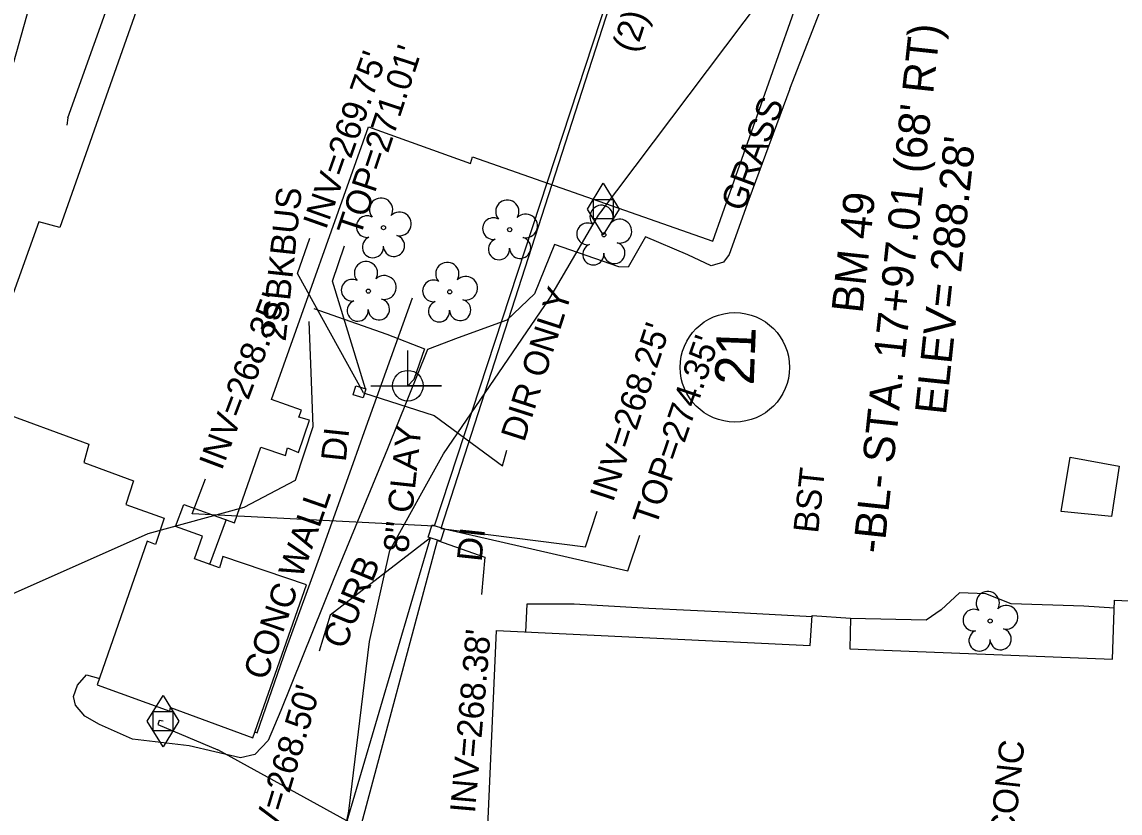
# Model space of a CAD drawing. Extents: x 2100323 to 2109811, y 740376 to 749755.
# Drawn here: x 2105595 to 2105770.6, y 741876.3 to 742002.8 of the extents above; entities that cross this region are included whole.
import ezdxf

# ---------------------------------------------------------------- set-up
doc = ezdxf.new("R2010")
doc.units = 0
for name, color, linetype in [('CTL Sheet Text', 7, 'Continuous'), ('Exist Building', 7, 'Continuous'), ('Exist Building Text', 7, 'Continuous'), ('Exist Property Owner Number CELL', 7, 'Continuous'), ('Exist Roads Change in Surface', 7, 'Continuous'), ('Exist Roads EOP Other', 7, 'Continuous'), ('Exist Roads EOP Other Text', 7, 'Continuous'), ('Exist Roads EOP Text', 7, 'Continuous'), ('Exist Structure Minor Drop Inlet', 7, 'Continuous'), ('Exist Structure Minor Drop Inlet Text', 7, 'Continuous'), ('Exist Structure Minor Drop Inlet Top Elevation', 7, 'Continuous'), ('Exist Structure Minor Pipes HDPE 8 Inch', 7, 'Continuous'), ('Exist Structure Minor Pipes HDPE 8 Inch Invert', 7, 'Continuous'), ('Exist Structure Minor Pipes HDPE 8 Inch Leader', 7, 'Continuous'), ('Exist Structure Minor Pipes HDPE 8 Inch Text', 7, 'Continuous'), ('Exist Structure Minor Pipes RCP 30 Inch', 7, 'Continuous'), ('Exist Structure Minor Pipes RCP 30 Inch Invert', 7, 'Continuous'), ('Exist Structure Minor Pipes RCP 30 Inch Leader', 7, 'Continuous'), ('Exist Structure Minor Pipes RCP 36 Inch', 7, 'Continuous'), ('Exist Structure Minor Pipes RCP 36 Inch Invert', 7, 'Continuous'), ('Exist Structure Minor Pipes RCP 36 Inch Leader', 7, 'Continuous'), ('Exist Structure Minor Pipes RCP 36 Inch Text', 7, 'Continuous'), ('Exist Utilities Gas Meter CELL', 7, 'Continuous'), ('Exist Utilities Gas UG Line SUE LOS B', 7, 'Continuous'), ('Exist Utilities Power Joint Use Telephone CELL', 7, 'Continuous'), ('Exist Utilities Power UG Cable SUE LOS B', 7, 'Continuous'), ('Exist Utilities TV UG Cable SUE LOS B', 7, 'Continuous'), ('Exist Utilities Water UG Line SUE LOS B', 7, 'Continuous'), ('Exist Vegetation Tree CELL', 7, 'Continuous')]:
    doc.layers.add(name, color=color, linetype=linetype)

msp = doc.modelspace()

# ---------------------------------------------------------------- linework, layer by layer
at = {"layer": 'Exist Building'}
for points in [[(2105621.62, 742028.24), (2105601.07, 741969.88), (2105597.69, 741970.78), (2105587.85, 741943.41)], [(2105590.56, 741940.79), (2105605.71, 741935.25), (2105604.88, 741932.34), (2105612.85, 741929.4), (2105611.59, 741925.61), (2105617.73, 741923.43), (2105616.34, 741919.21), (2105615.02, 741919.75), (2105607.01, 741896.76), (2105618.63, 741892.58), (2105618.76, 741893.15), (2105631.93, 741888.31), (2105640.48, 741912.76), (2105627.14, 741917.27), (2105626.57, 741915.46), (2105622.58, 741916.92), (2105623.85, 741920.55), (2105619.55, 741922.08), (2105620.87, 741925.6), (2105629.01, 741922.69), (2105633.22, 741934.75), (2105637.15, 741933.46), (2105637.44, 741934.67), (2105639.24, 741933.94), (2105641.01, 741939.07), (2105639.3, 741939.58), (2105639.68, 741940.69), (2105634.9, 741942.39), (2105650.4, 741985.99), (2105666.71, 741980.11), (2105667.07, 741981.21), (2105705.48, 741967.71), (2105725.59, 742024.56)], [(2105632.26, 741889.23), (2105632.61, 741889.09), (2105637.28, 741902.64), (2105642.8, 741917.71), (2105647.96, 741932.16), (2105649.77, 741937.29), (2105657.47, 741958.64)]]:
    msp.add_lwpolyline(points, dxfattribs=at)
msp.add_lwpolyline([(2105670.9, 741905.44), (2105721.05, 741903.04), (2105721.37, 741907.86), (2105727.5, 741907.41), (2105727.43, 741902.52), (2105769.41, 741900.88), (2105769.76, 741910.32), (2105844.65, 741906.94), (2105842.98, 741859.96), (2105839.73, 741860.04), (2105839.3, 741846.45), (2105817.52, 741847.26), (2105817.67, 741848.94), (2105747.32, 741852.58), (2105747.94, 741861.98), (2105669.16, 741865.67)], close=True, dxfattribs=at)
at = {"layer": 'Exist Property Owner Number CELL'}
msp.add_circle((2105709.01, 741947.53), 8.75, dxfattribs=at)
at = {"layer": 'Exist Roads Change in Surface'}
msp.add_lwpolyline([(2105769.28, 741923.68), (2105761.19, 741924.49), (2105762.63, 741933.18), (2105770.47, 741931.72), (2105769.28, 741923.68)], dxfattribs=at)
at = {"layer": 'Exist Roads EOP Other'}
for points in [[(2105717.81, 741992.04), (2105723.84, 742007.6), (2105728.39, 742018.84), (2105729.19, 742021.25), (2105728.91, 742023.26), (2105727.58, 742024.18), (2105725.48, 742023.47)], [(2105717.81, 741992.04), (2105711.27, 741974.37), (2105708.1, 741965.56), (2105707.2, 741964.35), (2105705.22, 741963.79), (2105701.48, 741965.51), (2105694.75, 741968.38), (2105692.78, 741965.03), (2105691.97, 741963.57), (2105690.48, 741963.59), (2105680.16, 741967.17), (2105676.99, 741959.3), (2105672.53, 741955.06), (2105664.76, 741952.27), (2105659.87, 741950.38), (2105653.45, 741934.5), (2105644.89, 741913.69), (2105636.4, 741892.69), (2105634.38, 741887.87), (2105632.25, 741885.64), (2105629.95, 741885.1), (2105621.73, 741887.04), (2105612.69, 741888.09), (2105607.37, 741890.44), (2105605.07, 741891.77), (2105603.55, 741893.51), (2105603.23, 741894.89), (2105603.89, 741896.72), (2105605.3, 741898.35), (2105607.26, 741897.86), (2105607.38, 741897.83)], [(2105627.64, 741923.18), (2105625.01, 741916.03)], [(2105769.72, 741909.05), (2105764.85, 741909.37), (2105753.19, 741909.71), (2105749.15, 741911.34), (2105744.94, 741911.49), (2105742.02, 741908.76), (2105739.64, 741907.11), (2105727.5, 741907.36)], [(2105721.36, 741907.64), (2105708.58, 741908.34), (2105695.28, 741908.98), (2105683.34, 741909.69), (2105675.73, 741909.67), (2105675.53, 741905.21)]]:
    msp.add_lwpolyline(points, dxfattribs=at)
at = {"layer": 'Exist Structure Minor Drop Inlet'}
for points in [[(2105648.4, 741944.58), (2105649.97, 741944.12), (2105649.55, 741942.67), (2105647.98, 741943.13)], [(2105660.59, 741922.36), (2105662.56, 741921.7), (2105661.91, 741919.74), (2105659.94, 741920.4)]]:
    msp.add_lwpolyline(points, close=True, dxfattribs=at)
at = {"layer": 'Exist Structure Minor Drop Inlet Top Elevation'}
for points in [[(2105649.95, 741944.12), (2105644.68, 741961.29), (2105646.56, 741966.98)], [(2105662.56, 741921.7), (2105691.89, 741915.01), (2105693.83, 741920.68)]]:
    msp.add_lwpolyline(points, dxfattribs=at)
at = {"layer": 'Exist Structure Minor Pipes HDPE 8 Inch'}
msp.add_line((2105649.63, 741943.44), (2105660.95, 741939.84), dxfattribs=at)
at = {"layer": 'Exist Structure Minor Pipes HDPE 8 Inch Leader'}
for points in [[(2105649.63, 741943.44), (2105639.07, 741962.52), (2105641.06, 741968.17)], [(2105660.95, 741939.84), (2105671.85, 741931.77), (2105672.53, 741934.29)]]:
    msp.add_lwpolyline(points, dxfattribs=at)
at = {"layer": 'Exist Structure Minor Pipes RCP 30 Inch'}
for p, q in [((2105643.15, 741861.99), (2105660.33, 741920.28)), ((2105645.68, 741860.94), (2105661.47, 741919.87))]:
    msp.add_line(p, q, dxfattribs=at)
at = {"layer": 'Exist Structure Minor Pipes RCP 30 Inch Leader'}
for points in [[(2105660.33, 741920.28), (2105644.27, 741907.92), (2105642.54, 741902.17)], [(2105661.47, 741919.87), (2105669.02, 741917.18), (2105668.5, 741911.2)]]:
    msp.add_lwpolyline(points, dxfattribs=at)
at = {"layer": 'Exist Structure Minor Pipes RCP 36 Inch'}
for q in [(2105660.92, 741922.15), (2105662.01, 741921.74)]:
    msp.add_line((2105724.03, 742114.27), q, dxfattribs=at)
at = {"layer": 'Exist Structure Minor Pipes RCP 36 Inch Leader'}
for points in [[(2105660.92, 741922.15), (2105622.24, 741924.12), (2105624.36, 741929.73)], [(2105662.01, 741921.74), (2105685.12, 741918.85), (2105686.99, 741924.55)]]:
    msp.add_lwpolyline(points, dxfattribs=at)
at = {"layer": 'Exist Utilities Gas Meter CELL'}
for p, q in [((2105687.97, 741972.85), (2105687.97, 741972.85)), ((2105617.56, 741890.97), (2105617.56, 741890.97))]:
    msp.add_line(p, q, dxfattribs=at)
for points in [[(2105685.43, 741972.85), (2105687.97, 741976.96), (2105690.51, 741972.85), (2105687.97, 741968.73), (2105685.43, 741972.85)], [(2105686.4, 741974.38), (2105689.55, 741974.38), (2105689.55, 741971.27), (2105686.4, 741971.27), (2105686.4, 741974.38)], [(2105615.02, 741890.97), (2105617.56, 741895.08), (2105620.09, 741890.97), (2105617.56, 741886.86), (2105615.02, 741890.97)], [(2105615.98, 741892.51), (2105619.13, 741892.51), (2105619.13, 741889.4), (2105615.98, 741889.4), (2105615.98, 741892.51)]]:
    msp.add_lwpolyline(points, dxfattribs=at)
at = {"layer": 'Exist Utilities Gas UG Line SUE LOS B'}
for p, q in [((2105687.22, 741971.84), (2105726.06, 742023.43)), ((2105687.22, 741971.84), (2105687.97, 741972.85)), ((2105617.56, 741890.97), (2105616.92, 741891.09)), ((2105646.94, 741875.02), (2105626.33, 741886.37))]:
    msp.add_line(p, q, dxfattribs=at)
for points in [[(2105647.25, 741876.57), (2105650.56, 741903.7), (2105653.84, 741918.27), (2105662.41, 741933.73), (2105679.43, 741958.59), (2105687.22, 741971.84)], [(2105616.92, 741891.09), (2105616.75, 741890.43), (2105626.33, 741886.37)], [(2105653.36, 741871.99), (2105646.94, 741875.02), (2105647.25, 741876.57)]]:
    msp.add_lwpolyline(points, dxfattribs=at)
at = {"layer": 'Exist Utilities Power Joint Use Telephone CELL'}
msp.add_line((2105656.72, 741944.6), (2105656.72, 741944.6), dxfattribs=at)
msp.add_lwpolyline([(2105650.78, 741944.6), (2105662.12, 741944.56), (2105656.72, 741944.58), (2105656.72, 741950.22)], dxfattribs=at)
msp.add_circle((2105656.72, 741944.6), 2.45, dxfattribs=at)
at = {"layer": 'Exist Utilities Power UG Cable SUE LOS B'}
msp.add_line((2105656.72, 741944.6), (2105657.67, 741945.59), dxfattribs=at)
msp.add_lwpolyline([(2105641.66, 741956.96), (2105653.34, 741952.84), (2105659.38, 741950.49), (2105657.67, 741945.59)], dxfattribs=at)
at = {"layer": 'Exist Utilities TV UG Cable SUE LOS B'}
for points in [[(2105527.57, 742109.95), (2105528.48, 742108.03), (2105531.48, 742106.55), (2105550.94, 742100.66), (2105578.9, 742090.61), (2105608.91, 742080.59), (2105614.57, 742077.87), (2105615.9, 742075.61), (2105615.54, 742071.58), (2105612.36, 742057.27), (2105605.05, 742034.49), (2105599.03, 742015.51), (2105593.63, 741996.28)], [(2105589.63, 741984.27), (2105580.07, 741956.01), (2105575.61, 741943.38), (2105572.91, 741923.46), (2105575.07, 741905), (2105576.12, 741902.65), (2105578.15, 741902.39), (2105592.98, 741911.12), (2105615.17, 741920.96), (2105630.55, 741925.15), (2105638.77, 741929.49), (2105641.57, 741938.07), (2105641.24, 741946.71), (2105640.95, 741954.88)]]:
    msp.add_lwpolyline(points, dxfattribs=at)
at = {"layer": 'Exist Utilities Water UG Line SUE LOS B'}
msp.add_line((2105602.34, 741987.45), (2105602.16, 741986.27), dxfattribs=at)
msp.add_lwpolyline([(2105602.34, 741987.45), (2105610.73, 742011.04), (2105618.6, 742034.58), (2105628.65, 742063.88)], dxfattribs=at)
at = {"layer": 'Exist Vegetation Tree CELL'}
for p, q in [((2105652.82, 741969.87), (2105652.82, 741969.87)), ((2105673, 741969.55), (2105673, 741969.55)), ((2105688.07, 741968.72), (2105688.07, 741968.72)), ((2105650.4, 741959.72), (2105650.4, 741959.72)), ((2105663.41, 741959.6), (2105663.41, 741959.6)), ((2105749.85, 741906.97), (2105749.85, 741906.97))]:
    msp.add_line(p, q, dxfattribs=at)
for centre in [(2105652.82, 741969.87), (2105673, 741969.55), (2105688.07, 741968.72), (2105650.4, 741959.72), (2105663.41, 741959.6), (2105749.85, 741906.97)]:
    msp.add_circle(centre, 0.326, dxfattribs=at)
for centre, radius, start, end in [((2105652.43, 741972.75), 1.86, 330.1651, 219.7134), ((2105672.62, 741972.43), 1.86, 330.1651, 219.7134), ((2105687.69, 741971.59), 1.86, 330.1651, 219.7134), ((2105650.21, 741970.03), 1.73, 62.6636, 279.3457), ((2105655.37, 741970.46), 1.9, 257.1011, 134.1999), ((2105675.55, 741970.14), 1.9, 257.1011, 134.1999), ((2105670.4, 741969.71), 1.73, 62.6636, 279.3457), ((2105685.46, 741968.87), 1.73, 62.6636, 279.3457), ((2105690.62, 741969.31), 1.9, 257.1011, 134.1999), ((2105651.12, 741966.75), 1.69, 111.5671, 6.231), ((2105654.49, 741966.97), 1.7, 181.2822, 74.56), ((2105671.3, 741966.43), 1.69, 111.5671, 6.231), ((2105674.68, 741966.65), 1.7, 181.2822, 74.56), ((2105686.37, 741965.6), 1.69, 111.5671, 6.231), ((2105689.74, 741965.82), 1.7, 181.2822, 74.56), ((2105650.02, 741962.59), 1.86, 330.1651, 219.7134), ((2105663.03, 741962.47), 1.86, 330.1651, 219.7134), ((2105647.8, 741959.87), 1.73, 62.6636, 279.3457), ((2105652.95, 741960.3), 1.9, 257.1011, 134.1999), ((2105660.81, 741959.75), 1.73, 62.6636, 279.3457), ((2105665.96, 741960.19), 1.9, 257.1011, 134.1999), ((2105648.7, 741956.6), 1.69, 111.5671, 6.231), ((2105652.08, 741956.82), 1.7, 181.2822, 74.56), ((2105661.71, 741956.48), 1.69, 111.5671, 6.231), ((2105665.08, 741956.7), 1.7, 181.2822, 74.56), ((2105749.47, 741909.84), 1.86, 330.1651, 219.7134), ((2105747.25, 741907.12), 1.73, 62.6636, 279.3457), ((2105752.4, 741907.56), 1.9, 257.1011, 134.1999), ((2105748.15, 741903.85), 1.69, 111.5671, 6.231), ((2105751.52, 741904.07), 1.7, 181.2822, 74.56)]:
    msp.add_arc(centre, radius, start, end, dxfattribs=at)

# ---------------------------------------------------------------- texts
at = {"layer": 'CTL Sheet Text'}
for s, p in [("-BL- STA. 17+97.01 (68' RT)", (2105732.85, 741917.64)), ("ELEV= 288.28'", (2105742.77, 741939.82)), ('BM 49', (2105729.43, 741956.06))]:
    msp.add_text(s, height=5, rotation=83.8864, dxfattribs=at).set_placement(p)
at = {"layer": 'Exist Building Text'}
for s, rotation, p in [('2SBKBUS', 83.8864, (2105637.16, 741951.6)), ('CONC WALL', 70.8643, (2105634.07, 741897.31))]:
    msp.add_text(s, height=4, rotation=rotation, dxfattribs=at).set_placement(p)
at = {"layer": 'Exist Property Owner Number CELL'}
msp.add_text('21', height=6.25, rotation=87.7944, dxfattribs=at).set_placement((2105712.03, 741944.61))
at = {"layer": 'Exist Roads EOP Other Text'}
for s, rotation, p in [('GRASS', 69.6916, (2105710.43, 741972.25)), ('CURB', 67.6446, (2105646.6, 741902.26)), ('CONC', 83.8864, (2105753.71, 741872.07))]:
    msp.add_text(s, height=4, rotation=rotation, dxfattribs=at).set_placement(p)
at = {"layer": 'Exist Roads EOP Text'}
msp.add_text('BST', height=4, rotation=83.8864, dxfattribs=at).set_placement((2105722.33, 741920.89))
at = {"layer": 'Exist Structure Minor Drop Inlet Text'}
for p in [(2105646.78, 741932.34), (2105668.51, 741916.35)]:
    msp.add_text('DI', height=4, rotation=83.8864, dxfattribs=at).set_placement(p)
at = {"layer": 'Exist Structure Minor Drop Inlet Top Elevation'}
for s, rotation, p in [("TOP=271.01'", 71.6552, (2105649.09, 741968.25)), ("TOP=274.35'", 71.0996, (2105696.37, 741921.93))]:
    msp.add_text(s, height=4, rotation=rotation, dxfattribs=at).set_placement(p)
at = {"layer": 'Exist Structure Minor Pipes HDPE 8 Inch Invert'}
for s, rotation, p in [("INV=269.75'", 70.5687, (2105643.61, 741969.4)), ('DIR ONLY', 72.2385, (2105675.31, 741935.45))]:
    msp.add_text(s, height=4, rotation=rotation, dxfattribs=at).set_placement(p)
at = {"layer": 'Exist Structure Minor Pipes HDPE 8 Inch Text'}
msp.add_text('8" CLAY', height=4, rotation=83.8864, dxfattribs=at).set_placement((2105656.75, 741917.78))
at = {"layer": 'Exist Structure Minor Pipes RCP 30 Inch Invert'}
for s, rotation, p in [("INV=268.38'", 85, (2105667.44, 741876.15)), ("INV=268.50'", 73.2583, (2105634.28, 741867.77))]:
    msp.add_text(s, height=4, rotation=rotation, dxfattribs=at).set_placement(p)
at = {"layer": 'Exist Structure Minor Pipes RCP 36 Inch Invert'}
for s, rotation, p in [("INV=268.35'", 69.3304, (2105626.94, 741930.9)), ("INV=268.25'", 71.8178, (2105689.52, 741925.83))]:
    msp.add_text(s, height=4, rotation=rotation, dxfattribs=at).set_placement(p)
at = {"layer": 'Exist Structure Minor Pipes RCP 36 Inch Text'}
msp.add_text('(2)', height=4, rotation=72.1446, dxfattribs=at).set_placement((2105693.16, 741997.64))

doc.saveas('drawing.dxf')
